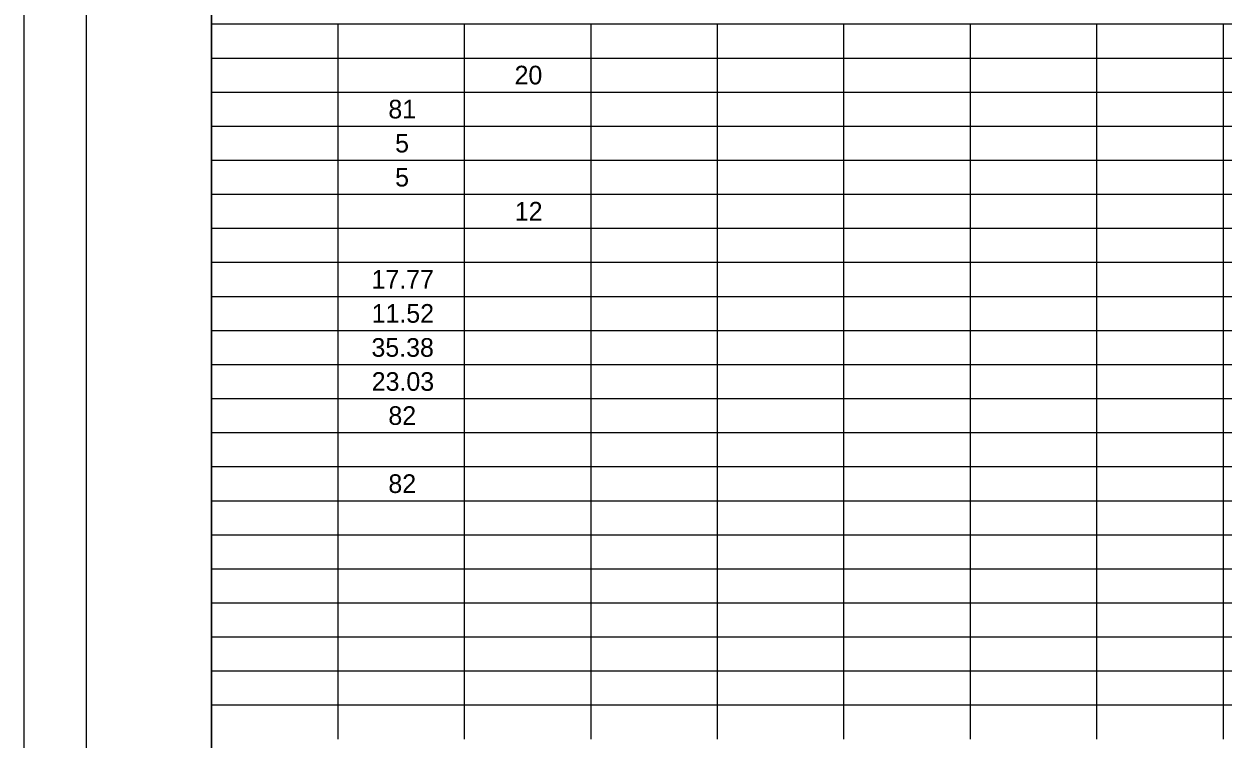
# Model space of a CAD drawing. Extents: x 0 to 34, y 0 to 22.
# Drawn here: x 0 to 9.6, y 10.33 to 16.05 of the extents above; entities that cross this region are included whole.
import ezdxf

# ---------------------------------------------------------------- set-up
doc = ezdxf.new("R2010")
doc.units = 0
for name, color, linetype in [('Default', 7, 'Continuous'), ('SH_Border', 7, 'Continuous'), ('SH_Cut_Line', 7, 'Continuous')]:
    doc.layers.add(name, color=color, linetype=linetype)

msp = doc.modelspace()

# ---------------------------------------------------------------- linework, layer by layer
at = {"layer": 'Default'}
for p, q in [((1.5, 16.0494), (2.5123, 16.0494)), ((1.5, 16.0494), (1.5, 15.7768)), ((2.5123, 16.0494), (3.5245, 16.0494)), ((2.5123, 16.0494), (2.5123, 15.7768)), ((3.5245, 16.0494), (4.5368, 16.0494)), ((3.5245, 16.0494), (3.5245, 15.7768)), ((4.5368, 16.0494), (5.549, 16.0494)), ((4.5368, 16.0494), (4.5368, 15.7768)), ((5.549, 16.0494), (6.5613, 16.0494)), ((5.549, 16.0494), (5.549, 15.7768)), ((6.5613, 16.0494), (7.5736, 16.0494)), ((6.5613, 16.0494), (6.5613, 15.7768)), ((7.5736, 16.0494), (8.5858, 16.0494)), ((7.5736, 16.0494), (7.5736, 15.7768)), ((8.5858, 16.0494), (9.5981, 16.0494)), ((8.5858, 16.0494), (8.5858, 15.7768)), ((9.5981, 16.0494), (11.6226, 16.0494)), ((9.5981, 16.0494), (9.5981, 15.7768)), ((1.5, 15.7768), (2.5123, 15.7768)), ((1.5, 15.7768), (1.5, 15.5043)), ((2.5123, 15.7768), (3.5245, 15.7768)), ((2.5123, 15.7768), (2.5123, 15.5043)), ((3.5245, 15.7768), (4.5368, 15.7768)), ((3.5245, 15.7768), (3.5245, 15.5043)), ((4.5368, 15.7768), (5.549, 15.7768)), ((4.5368, 15.7768), (4.5368, 15.5043)), ((5.549, 15.7768), (6.5613, 15.7768)), ((5.549, 15.7768), (5.549, 15.5043)), ((6.5613, 15.7768), (7.5736, 15.7768)), ((6.5613, 15.7768), (6.5613, 15.5043)), ((7.5736, 15.7768), (8.5858, 15.7768)), ((7.5736, 15.7768), (7.5736, 15.5043)), ((8.5858, 15.7768), (9.5981, 15.7768)), ((8.5858, 15.7768), (8.5858, 15.5043)), ((9.5981, 15.7768), (11.6226, 15.7768)), ((9.5981, 15.7768), (9.5981, 15.5043)), ((1.5, 15.5043), (2.5123, 15.5043)), ((1.5, 15.5043), (1.5, 14.9592)), ((2.5123, 15.5043), (3.5245, 15.5043)), ((2.5123, 15.5043), (2.5123, 14.9592)), ((3.5245, 15.5043), (4.5368, 15.5043)), ((3.5245, 15.5043), (3.5245, 14.9592)), ((4.5368, 15.5043), (5.549, 15.5043)), ((4.5368, 15.5043), (4.5368, 14.9592)), ((5.549, 15.5043), (6.5613, 15.5043)), ((5.549, 15.5043), (5.549, 14.9592)), ((6.5613, 15.5043), (7.5736, 15.5043)), ((6.5613, 15.5043), (6.5613, 14.9592)), ((7.5736, 15.5043), (8.5858, 15.5043)), ((7.5736, 15.5043), (7.5736, 14.9592)), ((8.5858, 15.5043), (9.5981, 15.5043)), ((8.5858, 15.5043), (8.5858, 14.9592)), ((9.5981, 15.5043), (11.6226, 15.5043)), ((9.5981, 15.5043), (9.5981, 14.9592)), ((1.5, 15.2318), (2.5123, 15.2318)), ((2.5123, 15.2318), (3.5245, 15.2318)), ((3.5245, 15.2318), (4.5368, 15.2318)), ((4.5368, 15.2318), (5.549, 15.2318)), ((5.549, 15.2318), (6.5613, 15.2318)), ((6.5613, 15.2318), (7.5736, 15.2318)), ((7.5736, 15.2318), (8.5858, 15.2318)), ((8.5858, 15.2318), (9.5981, 15.2318)), ((9.5981, 15.2318), (11.6226, 15.2318)), ((1.5, 14.9592), (2.5123, 14.9592)), ((1.5, 14.9592), (1.5, 14.6867)), ((2.5123, 14.9592), (3.5245, 14.9592)), ((2.5123, 14.9592), (2.5123, 14.6867)), ((3.5245, 14.9592), (4.5368, 14.9592)), ((3.5245, 14.9592), (3.5245, 14.6867)), ((4.5368, 14.9592), (5.549, 14.9592)), ((4.5368, 14.9592), (4.5368, 14.6867)), ((5.549, 14.9592), (6.5613, 14.9592)), ((5.549, 14.9592), (5.549, 14.6867)), ((6.5613, 14.9592), (7.5736, 14.9592)), ((6.5613, 14.9592), (6.5613, 14.6867)), ((7.5736, 14.9592), (8.5858, 14.9592)), ((7.5736, 14.9592), (7.5736, 14.6867)), ((8.5858, 14.9592), (9.5981, 14.9592)), ((8.5858, 14.9592), (8.5858, 14.6867)), ((9.5981, 14.9592), (11.6226, 14.9592)), ((9.5981, 14.9592), (9.5981, 14.6867)), ((1.5, 14.6867), (2.5123, 14.6867)), ((1.5, 14.6867), (1.5, 14.4142)), ((2.5123, 14.6867), (3.5245, 14.6867)), ((2.5123, 14.6867), (2.5123, 14.4142)), ((3.5245, 14.6867), (4.5368, 14.6867)), ((3.5245, 14.6867), (3.5245, 14.4142)), ((4.5368, 14.6867), (5.549, 14.6867)), ((4.5368, 14.6867), (4.5368, 14.4142)), ((5.549, 14.6867), (6.5613, 14.6867)), ((5.549, 14.6867), (5.549, 14.4142)), ((6.5613, 14.6867), (7.5736, 14.6867)), ((6.5613, 14.6867), (6.5613, 14.4142)), ((7.5736, 14.6867), (8.5858, 14.6867)), ((7.5736, 14.6867), (7.5736, 14.4142)), ((8.5858, 14.6867), (9.5981, 14.6867)), ((8.5858, 14.6867), (8.5858, 14.4142)), ((9.5981, 14.6867), (11.6226, 14.6867)), ((9.5981, 14.6867), (9.5981, 14.4142)), ((1.5, 14.4142), (2.5123, 14.4142)), ((1.5, 14.4142), (1.5, 14.1416)), ((2.5123, 14.4142), (3.5245, 14.4142)), ((2.5123, 14.4142), (2.5123, 14.1416)), ((3.5245, 14.4142), (4.5368, 14.4142)), ((3.5245, 14.4142), (3.5245, 14.1416)), ((4.5368, 14.4142), (5.549, 14.4142)), ((4.5368, 14.4142), (4.5368, 14.1416)), ((5.549, 14.4142), (6.5613, 14.4142)), ((5.549, 14.4142), (5.549, 14.1416)), ((6.5613, 14.4142), (7.5736, 14.4142)), ((6.5613, 14.4142), (6.5613, 14.1416)), ((7.5736, 14.4142), (8.5858, 14.4142)), ((7.5736, 14.4142), (7.5736, 14.1416)), ((8.5858, 14.4142), (9.5981, 14.4142)), ((8.5858, 14.4142), (8.5858, 14.1416)), ((9.5981, 14.4142), (11.6226, 14.4142)), ((9.5981, 14.4142), (9.5981, 14.1416)), ((1.5, 14.1416), (2.5123, 14.1416)), ((1.5, 14.1416), (1.5, 11.9614)), ((2.5123, 14.1416), (3.5245, 14.1416)), ((2.5123, 14.1416), (2.5123, 11.9614)), ((3.5245, 14.1416), (4.5368, 14.1416)), ((3.5245, 14.1416), (3.5245, 11.9614)), ((4.5368, 14.1416), (5.549, 14.1416)), ((4.5368, 14.1416), (4.5368, 11.9614)), ((5.549, 14.1416), (6.5613, 14.1416)), ((5.549, 14.1416), (5.549, 11.9614)), ((6.5613, 14.1416), (7.5736, 14.1416)), ((6.5613, 14.1416), (6.5613, 11.9614)), ((7.5736, 14.1416), (8.5858, 14.1416)), ((7.5736, 14.1416), (7.5736, 11.9614)), ((8.5858, 14.1416), (9.5981, 14.1416)), ((8.5858, 14.1416), (8.5858, 11.9614)), ((9.5981, 14.1416), (11.6226, 14.1416)), ((9.5981, 14.1416), (9.5981, 11.9614)), ((1.5, 13.8691), (2.5123, 13.8691)), ((2.5123, 13.8691), (3.5245, 13.8691)), ((3.5245, 13.8691), (4.5368, 13.8691)), ((4.5368, 13.8691), (5.549, 13.8691)), ((5.549, 13.8691), (6.5613, 13.8691)), ((6.5613, 13.8691), (7.5736, 13.8691)), ((7.5736, 13.8691), (8.5858, 13.8691)), ((8.5858, 13.8691), (9.5981, 13.8691)), ((9.5981, 13.8691), (11.6226, 13.8691)), ((1.5, 13.5966), (2.5123, 13.5966)), ((2.5123, 13.5966), (3.5245, 13.5966)), ((3.5245, 13.5966), (4.5368, 13.5966)), ((4.5368, 13.5966), (5.549, 13.5966)), ((5.549, 13.5966), (6.5613, 13.5966)), ((6.5613, 13.5966), (7.5736, 13.5966)), ((7.5736, 13.5966), (8.5858, 13.5966)), ((8.5858, 13.5966), (9.5981, 13.5966)), ((9.5981, 13.5966), (11.6226, 13.5966)), ((1.5, 13.324), (2.5123, 13.324)), ((2.5123, 13.324), (3.5245, 13.324)), ((3.5245, 13.324), (4.5368, 13.324)), ((4.5368, 13.324), (5.549, 13.324)), ((5.549, 13.324), (6.5613, 13.324)), ((6.5613, 13.324), (7.5736, 13.324)), ((7.5736, 13.324), (8.5858, 13.324)), ((8.5858, 13.324), (9.5981, 13.324)), ((9.5981, 13.324), (11.6226, 13.324)), ((1.5, 13.0515), (2.5123, 13.0515)), ((2.5123, 13.0515), (3.5245, 13.0515)), ((3.5245, 13.0515), (4.5368, 13.0515)), ((4.5368, 13.0515), (5.549, 13.0515)), ((5.549, 13.0515), (6.5613, 13.0515)), ((6.5613, 13.0515), (7.5736, 13.0515)), ((7.5736, 13.0515), (8.5858, 13.0515)), ((8.5858, 13.0515), (9.5981, 13.0515)), ((9.5981, 13.0515), (11.6226, 13.0515)), ((1.5, 12.779), (2.5123, 12.779)), ((2.5123, 12.779), (3.5245, 12.779)), ((3.5245, 12.779), (4.5368, 12.779)), ((4.5368, 12.779), (5.549, 12.779)), ((5.549, 12.779), (6.5613, 12.779)), ((6.5613, 12.779), (7.5736, 12.779)), ((7.5736, 12.779), (8.5858, 12.779)), ((8.5858, 12.779), (9.5981, 12.779)), ((9.5981, 12.779), (11.6226, 12.779)), ((1.5, 12.5065), (2.5123, 12.5065)), ((2.5123, 12.5065), (3.5245, 12.5065)), ((3.5245, 12.5065), (4.5368, 12.5065)), ((4.5368, 12.5065), (5.549, 12.5065)), ((5.549, 12.5065), (6.5613, 12.5065)), ((6.5613, 12.5065), (7.5736, 12.5065)), ((7.5736, 12.5065), (8.5858, 12.5065)), ((8.5858, 12.5065), (9.5981, 12.5065)), ((9.5981, 12.5065), (11.6226, 12.5065)), ((1.5, 12.2339), (2.5123, 12.2339)), ((2.5123, 12.2339), (3.5245, 12.2339)), ((3.5245, 12.2339), (4.5368, 12.2339)), ((4.5368, 12.2339), (5.549, 12.2339)), ((5.549, 12.2339), (6.5613, 12.2339)), ((6.5613, 12.2339), (7.5736, 12.2339)), ((7.5736, 12.2339), (8.5858, 12.2339)), ((8.5858, 12.2339), (9.5981, 12.2339)), ((9.5981, 12.2339), (11.6226, 12.2339)), ((1.5, 11.9614), (2.5123, 11.9614)), ((1.5, 11.9614), (1.5, 11.6889)), ((2.5123, 11.9614), (3.5245, 11.9614)), ((2.5123, 11.9614), (2.5123, 11.6889)), ((3.5245, 11.9614), (4.5368, 11.9614)), ((3.5245, 11.9614), (3.5245, 11.6889)), ((4.5368, 11.9614), (5.549, 11.9614)), ((4.5368, 11.9614), (4.5368, 11.6889)), ((5.549, 11.9614), (6.5613, 11.9614)), ((5.549, 11.9614), (5.549, 11.6889)), ((6.5613, 11.9614), (7.5736, 11.9614)), ((6.5613, 11.9614), (6.5613, 11.6889)), ((7.5736, 11.9614), (8.5858, 11.9614)), ((7.5736, 11.9614), (7.5736, 11.6889)), ((8.5858, 11.9614), (9.5981, 11.9614)), ((8.5858, 11.9614), (8.5858, 11.6889)), ((9.5981, 11.9614), (11.6226, 11.9614)), ((9.5981, 11.9614), (9.5981, 11.6889)), ((1.5, 11.6889), (2.5123, 11.6889)), ((1.5, 11.6889), (1.5, 10.5987)), ((2.5123, 11.6889), (3.5245, 11.6889)), ((2.5123, 11.6889), (2.5123, 10.5987)), ((3.5245, 11.6889), (4.5368, 11.6889)), ((3.5245, 11.6889), (3.5245, 10.5987)), ((4.5368, 11.6889), (5.549, 11.6889)), ((4.5368, 11.6889), (4.5368, 10.5987)), ((5.549, 11.6889), (6.5613, 11.6889)), ((5.549, 11.6889), (5.549, 10.5987)), ((6.5613, 11.6889), (7.5736, 11.6889)), ((6.5613, 11.6889), (6.5613, 10.5987)), ((7.5736, 11.6889), (8.5858, 11.6889)), ((7.5736, 11.6889), (7.5736, 10.5987)), ((8.5858, 11.6889), (9.5981, 11.6889)), ((8.5858, 11.6889), (8.5858, 10.5987)), ((9.5981, 11.6889), (11.6226, 11.6889)), ((9.5981, 11.6889), (9.5981, 10.5987)), ((1.5, 11.4163), (2.5123, 11.4163)), ((2.5123, 11.4163), (3.5245, 11.4163)), ((3.5245, 11.4163), (4.5368, 11.4163)), ((4.5368, 11.4163), (5.549, 11.4163)), ((5.549, 11.4163), (6.5613, 11.4163)), ((6.5613, 11.4163), (7.5736, 11.4163)), ((7.5736, 11.4163), (8.5858, 11.4163)), ((8.5858, 11.4163), (9.5981, 11.4163)), ((9.5981, 11.4163), (11.6226, 11.4163)), ((1.5, 11.1438), (2.5123, 11.1438)), ((2.5123, 11.1438), (3.5245, 11.1438)), ((3.5245, 11.1438), (4.5368, 11.1438)), ((4.5368, 11.1438), (5.549, 11.1438)), ((5.549, 11.1438), (6.5613, 11.1438)), ((6.5613, 11.1438), (7.5736, 11.1438)), ((7.5736, 11.1438), (8.5858, 11.1438)), ((8.5858, 11.1438), (9.5981, 11.1438)), ((9.5981, 11.1438), (11.6226, 11.1438)), ((1.5, 10.8713), (2.5123, 10.8713)), ((2.5123, 10.8713), (3.5245, 10.8713)), ((3.5245, 10.8713), (4.5368, 10.8713)), ((4.5368, 10.8713), (5.549, 10.8713)), ((5.549, 10.8713), (6.5613, 10.8713)), ((6.5613, 10.8713), (7.5736, 10.8713)), ((7.5736, 10.8713), (8.5858, 10.8713)), ((8.5858, 10.8713), (9.5981, 10.8713)), ((9.5981, 10.8713), (11.6226, 10.8713)), ((1.5, 10.5987), (2.5123, 10.5987)), ((1.5, 10.5987), (1.5, 10.3262)), ((2.5123, 10.5987), (3.5245, 10.5987)), ((2.5123, 10.5987), (2.5123, 10.3262)), ((3.5245, 10.5987), (4.5368, 10.5987)), ((3.5245, 10.5987), (3.5245, 10.3262)), ((4.5368, 10.5987), (5.549, 10.5987)), ((4.5368, 10.5987), (4.5368, 10.3262)), ((5.549, 10.5987), (6.5613, 10.5987)), ((5.549, 10.5987), (5.549, 10.3262)), ((6.5613, 10.5987), (7.5736, 10.5987)), ((6.5613, 10.5987), (6.5613, 10.3262)), ((7.5736, 10.5987), (8.5858, 10.5987)), ((7.5736, 10.5987), (7.5736, 10.3262)), ((8.5858, 10.5987), (9.5981, 10.5987)), ((8.5858, 10.5987), (8.5858, 10.3262)), ((9.5981, 10.5987), (11.6226, 10.5987)), ((9.5981, 10.5987), (9.5981, 10.3262))]:
    msp.add_line(p, q, dxfattribs=at)
at = {"layer": 'SH_Border'}
for points in [[(0.5, 21.5), (1.5, 21.5), (1.5, 0.5), (0.5, 0.5)], [(1.5, 21.5), (33.5, 21.5), (33.5, 0.5), (1.5, 0.5)]]:
    msp.add_lwpolyline(points, close=True, dxfattribs=at)
at = {"layer": 'SH_Cut_Line'}
msp.add_lwpolyline([(0, 0), (34, 0), (34, 22), (0, 22)], close=True, dxfattribs=at)

# ---------------------------------------------------------------- texts
at = {"layer": 'Default'}
for s, height, p in [('20', 0.14924, (3.9271, 15.5659)), ('81', 0.14924, (2.9169, 15.2934)), ('5', 0.1492, (2.971, 15.0209)), ('5', 0.1492, (2.971, 14.7484)), ('12', 0.14924, (3.9293, 14.4758)), ('17.77', 0.14924, (2.7821, 13.9308)), ('11.52', 0.14924, (2.7831, 13.6582)), ('35.38', 0.14924, (2.7816, 13.3857)), ('23.03', 0.14924, (2.7837, 13.1132)), ('82', 0.14924, (2.9171, 12.8406)), ('82', 0.14924, (2.9171, 12.2956))]:
    msp.add_text(s, height=height, dxfattribs=at).set_placement(p)

doc.saveas('drawing.dxf')
